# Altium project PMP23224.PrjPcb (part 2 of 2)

## Sheet PMP23224_ACF_secondary.SchDoc
size 431 x 279 mm; Date: Not shown in title block; ApprovedBy: Not shown in title block; CheckedBy: Not shown in title block; Author: Not shown in title block; CompanyName: Not shown in title block; Engineer: Not shown in title block; Organization: Not shown in title block; Address1: Not shown in title block; Address2: Not shown in title block; Address3: Not shown in title block; Address4: Not shown in title block; DocumentNumber: 3; Revision: Use project parameter SCH_Rev; SheetNumber: 3; SheetTotal: 3; PageSetup: Record=PageOptions¦CenterHorizontal=True¦CenterVertical=True¦PrintScale=1.00¦XCorrection=1.00¦YCorrection=1.00¦PrintKind=0¦BorderSize=5000000¦LeftOffset=0¦BottomOffset=0¦Orientation=2¦PaperLength=1000¦PaperWidth=1000¦Scale=100¦PaperSource=15¦PrintQuality=600¦MediaType=1¦DitherType=10¦PaperKind=Letter¦PrintScaleMode=1
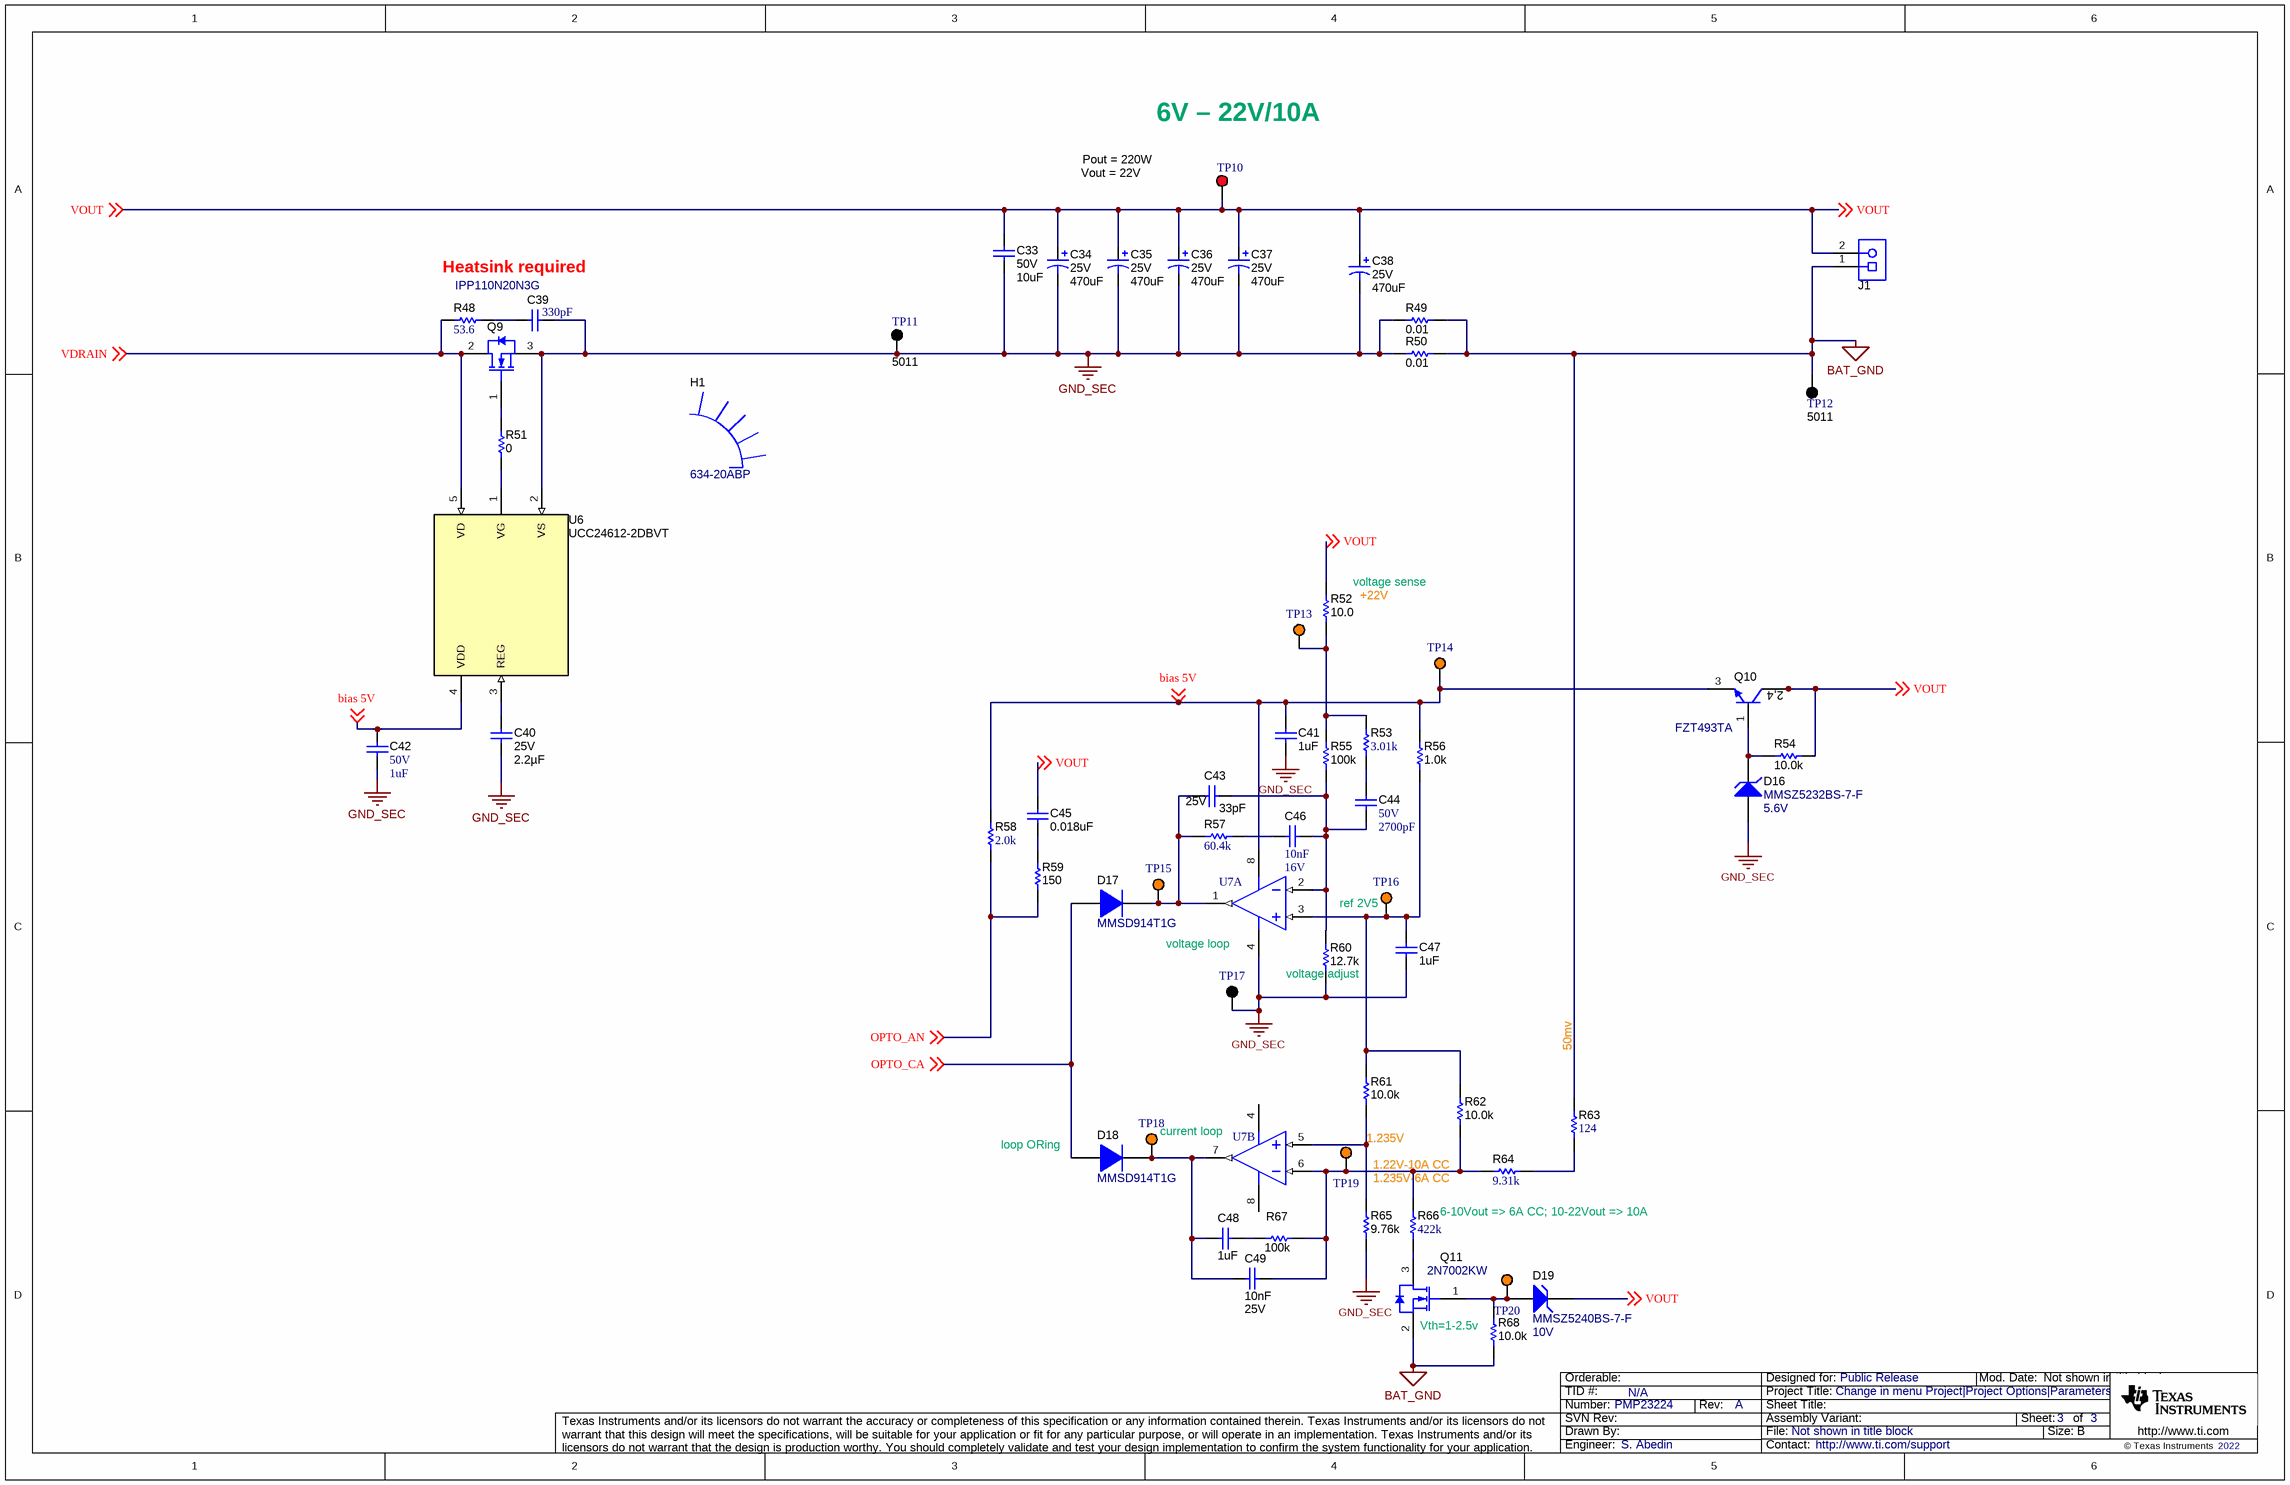
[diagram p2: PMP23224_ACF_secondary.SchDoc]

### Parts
C33  VDC_V: 50V  ValueDisplayed: 10uF  [1210_280]  (hidden comment: C3225X5R1H106K250AB)
C34  VDC_V: 25V  ValueDisplayed: 470uF  [Chemi-Con_1000x1600]  (hidden comment: ELXZ250ELL471MJ16S)
C35  VDC_V: 25V  ValueDisplayed: 470uF  [Chemi-Con_1000x1600]  (hidden comment: ELXZ250ELL471MJ16S)
C36  VDC_V: 25V  ValueDisplayed: 470uF  [Chemi-Con_1000x1600]  (hidden comment: ELXZ250ELL471MJ16S)
C37  VDC_V: 25V  ValueDisplayed: 470uF  [Chemi-Con_1000x1600]  (hidden comment: ELXZ250ELL471MJ16S)
C38  VDC_V: 25V  ValueDisplayed: 470uF  [Chemi-Con_1000x1600]  (hidden comment: ELXZ250ELL471MJ16S)
C39  ValueDisplayed: 330pF  [0805_HV]  (hidden comment: GRM21A5C2E331JW01D)
C40  VDC_V: 25V  ValueDisplayed: 2.2µF  [0603S]  (hidden comment: GRM188C71E225KE11D)
C41  ValueDisplayed: 1uF  [0603S]  (hidden comment: Capacitor)
C42  VDC_V: 50V  ValueDisplayed: 1uF  [0805_HV]  (hidden comment: C2012X5R1H105K125AB)
C43  VDC_V: 25V  ValueDisplayed: 33pF  [0402S]  (hidden comment: GRM1555C1E330JA01D)
C44  VDC_V: 50V  ValueDisplayed: 2700pF  [0402]  (hidden comment: GRM155R71H272KA01D)
C45  ValueDisplayed: 0.018uF  [0402S]  (hidden comment: GRM155R71H183KA12D)
C46  Cap_F: 10nF  VDC_V: 16V  [0603]  (hidden comment: GRM188R71C103KA01D)
C47  ValueDisplayed: 1uF  [0603S]  (hidden comment: Capacitor)
C48  ValueDisplayed: 1uF  [0603S]  (hidden comment: Capacitor)
C49  Cap_F: 10nF  VDC_V: 25V  [0603]  (hidden comment: GRM188R71E103KA01D)
D16  MMSZ5232BS-7-F  value 5.6V  [SOD-323]
D17  MMSD914T1G  [SOD-123]
D18  MMSD914T1G  [SOD-123]
D19  MMSZ5240BS-7-F  value 10V  [SOD-323]
H1  634-20ABP  [HSINK_634-10ABP]
J1  ED120/2DS  [On-Shore_ED120_2DS]  (value not drawn)
Q9  IPP110N20N3G  [TO-220-3]
Q10  FZT493TA  [SOT-223]
Q11  2N7002KW  [SOT-323]
R48  ValueDisplayed: 53.6  [0805_HV]  (hidden comment: RT0805BRD0753R6L)
R49  ValueDisplayed: 0.01  [2010]  (hidden comment: CSRN2010FT10L0)
R50  ValueDisplayed: 0.01  [2010]  (hidden comment: CSRN2010FT10L0)
R51  ValueDisplayed: 0  [0402S]  (hidden comment: CRCW04020000Z0ED)
R52  ValueDisplayed: 10.0  [0402]  (hidden comment: CRCW040210R0FKED)
R53  ValueDisplayed: 3.01k  [0402]  (hidden comment: CRCW04023K01FKED)
R54  ValueDisplayed: 10.0k  [1206]  (hidden comment: CRCW120610K0FKEA)
R55  ValueDisplayed: 100k  [0603S]  (hidden comment: Resistor)
R56  ValueDisplayed: 1.0k  [0603]  (hidden comment: CRCW06031K00JNEA)
R57  ValueDisplayed: 60.4k  [0603]  (hidden comment: CRCW060360K4FKEA)
R58  ValueDisplayed: 2.0k  [0603]  (hidden comment: CRCW06032K00JNEA)
R59  ValueDisplayed: 150  [0402S]  (hidden comment: CRCW0402150RFKED)
R60  ValueDisplayed: 12.7k  [0402S]  (hidden comment: CRCW040212K7FKED)
R61  ValueDisplayed: 10.0k  [TNPW0603]  (hidden comment: TNPW060310K0BEEA)
R62  ValueDisplayed: 10.0k  [TNPW0603]  (hidden comment: TNPW060310K0BEEA)
R63  ValueDisplayed: 124  [0402]  (hidden comment: CRCW0402124RFKED)
R64  ValueDisplayed: 9.31k  [0402]  (hidden comment: CRCW04029K31FKED)
R65  ValueDisplayed: 9.76k  [0603S]  (hidden comment: RG1608P-9761-B-T5)
R66  ValueDisplayed: 422k  [0402]  (hidden comment: CRCW0402422KFKED)
R67  ValueDisplayed: 100k  [0603S]  (hidden comment: Resistor)
R68  ValueDisplayed: 10.0k  [0603S]  (hidden comment: Resistor)
TP10  5010  [Keystone5010]  (value not drawn)
TP11  5011  [Keystone5011]
TP12  5011  [Keystone5011]
TP13  5003  [Keystone5003]  (value not drawn)
TP14  5003  [Keystone5003]  (value not drawn)
TP15  5003  [Keystone5003]  (value not drawn)
TP16  5003  [Keystone5003]  (value not drawn)
TP17  5001  [Keystone5001]  (value not drawn)
TP18  5003  [Keystone5003]  (value not drawn)
TP19  5003  [Keystone5003]  (value not drawn)
TP20  5003  [Keystone5003]  (value not drawn)
U6  UCC24612-2DBVT  [DBV0005A_N]
U7  TI-AMP-D6-2-8_D  [D0008A_N]  (value not drawn)  (parts A,B of 2)

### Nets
BAT_GND: J1.1 Q11.2(S) R49.2 R50.2 R63.2 R68.1 TP12.1
GND_SEC: C33.2 C34.2(-) C35.2(-) C36.2(-) C37.2(-) C38.2(-) C39.1 C40.2 C41.1 C42.2 C47.2 D16.2(A) Q9.3(S) R49.1 R50.1 R60.1 R65.1 TP11.1 TP17.1 U6.2(VS) U7.4(VCC-)
bias 5V: C41.2 C42.1 Q10.3(E) R56.2 R58.2 TP14.1 U6.4(VDD) U7.8(VCC+) ; off-sheet bias 5V
OPTO_AN: R58.1 R59.1 ; off-sheet OPTO_AN
OPTO_CA: D17.2(A) D18.2(A) ; off-sheet OPTO_CA
VDRAIN: Q9.2(D) R48.1 U6.5(VD) ; off-sheet VDRAIN
VOUT: C33.1 C34.1(+) C35.1(+) C36.1(+) C37.1(+) C38.1(+) C45.1 D19.1(K) J1.2 Q10.2(C) Q10.4(C) R52.2 R54.2 TP10.1 ; off-sheet VOUT
NetC39_2: C39.2 R48.2
NetC40_1: C40.1 U6.3(REG)
NetC43_1: C43.1 C44.2 C46.1 R55.1 R60.2 U7.2(IN1-)
NetC43_2: C43.2 D17.1(K) R57.1 TP15.1 U7.1(OUT1)
NetC44_1: C44.1 R53.1
NetC45_2: C45.2 R59.2
NetC46_2: C46.2 R57.2
NetC47_1: C47.1 R56.1 R61.2 R62.2 TP16.1 U7.3(IN1+)
NetC48_1: C48.1 C49.2 D18.1(K) TP18.1 U7.7(OUT2)
NetC48_2: C48.2 R67.2
NetC49_1: C49.1 R62.1 R64.1 R66.2 R67.1 TP19.1 U7.6(IN2-)
NetD16_1: D16.1(K) Q10.1(B) R54.1
NetD19_2: D19.2(A) Q11.1(G) R68.2 TP20.1
NetQ9_1: Q9.1(G) R51.1
NetQ11_3: Q11.3(D) R66.1
NetR51_2: R51.2 U6.1(VG)
NetR52_1: R52.1 R53.2 R55.2 TP13.1
NetR61_1: R61.1 R65.2 U7.5(IN2+)
NetR63_1: R63.1 R64.2

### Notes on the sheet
- Vout = 22V
- Pout = 220W
- 6V – 22V/10A
- Heatsink required
- (near R52) voltage sense
- (near R52) +22V
- (near TP16) ref 2V5
- (near U7) voltage loop
- (near R60) voltage adjust
- 50mv
- (near D18) loop ORing
- current loop
- 1.235V
- 1.22V-10A CC
- 1.235V-6A CC
- 6-10Vout => 6A CC; 10-22Vout => 10A
- Vth=1-2.5v

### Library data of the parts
C33 = CMP-0009103-1: CAP, CERM, 10 uF, 50 V, +/- 10%, X5R, 1210; Manufacturer: TDK; TaMin_C: -55°C; Polarized: N; SizeAreaWB_mm2: 14.7; Value1: Unknown; U/M: EA; Value: 10uF; TaMax_C: 85°C; SizeZ_mm: 2.8; SizeX_mm: 3.2; SizeY_mm: 2.5; Cap_Case: 1210; SizeArea_mm2: 8; Cap_F: 10µF; AEC Category: Q200
C34-C38 = CMP-0010480-1: CAP, AL, 470 uF, 25 V, +/- 20%, AEC-Q200 Grade 2, TH; Manufacturer: Chemi-Con; TaMin_C: -55°C; Polarized: Y; SizeAreaWB_mm2: 144; Value1: Unknown; U/M: EA; Value: 470uF; TaMax_C: 105°C; SizeZ_mm: 17.5; SizeX_mm: 10; Cap_Case: 10x16mm; SizeArea_mm2: 100; CompType: Capacitor; Cap_F: 470µF; IRMS_A: 1.05A; AEC Grade: 2; AEC Category: Q200
C39 = CMP-0081666-1: CAP, CERM, 330 pF, 250 V,+/- 5%, C0G/NP0, 0805; Manufacturer: MuRata; SizeAreaWB_mm2: 6.75; SizeArea_mm2: 2.5; AEC Qualified: N; AEC Category: Q200; Value: 330pF; TaMax_C: 125°C; SizeZ_mm: 1.45; TaMin_C: -55°C; VDC_V: 250V; SizeY_mm: 1.25; U/M: EA; CompType: Capacitor; SizeX_mm: 2; Cap_Case: 0805
C40 = CMP-0075366-1: CAP, CERM, 2.2 µF, 25 V,+/- 10%, X7S, 0603; Manufacturer: MuRata; TaMin_C: -55°C; Polarized: N; SizeAreaWB_mm2: 4.68; U/M: EA; Value: 2.2uF; TaMax_C: 125°C; SizeZ_mm: 1.0; SizeX_mm: 1.6; SizeY_mm: 0.8; Cap_Case: 0603; SizeArea_mm2: 1.28; AEC Category: Q200
C41 C47 C48 = CMP-0007405-4: CAP, CERM, 1 uF, 25 V, +/- 10%, X7R, 0603; PartNumber: GRM188R71E105KA12D; Manufacturer: MuRata; Polarized: N; Value: 1uF; U/M: EA; Cap_F: 1µF; Value1: Unknown; VDC_V: 25V; TaMin_C: -55°C; TaMax_C: 125°C; Cap_Case: 0603; AEC Category: Q200; SizeArea_mm2: 1.28; SizeAreaWB_mm2: 4.68; SizeX_mm: 1.6; SizeY_mm: 0.8; SizeZ_mm: 1
C42 = CMP-0007832-2: CAP, CERM, 1 uF, 50 V, +/- 10%, X5R, 0805; Manufacturer: TDK; TaMin_C: -55°C; ESR_ohm: 8.782m; Polarized: N; SizeAreaWB_mm2: 6.75; Value1: 0.008782 ohm; U/M: EA; Value: 1uF; TaMax_C: 85°C; SizeZ_mm: 1.45; SizeX_mm: 2; SizeY_mm: 1.25; Cap_Case: 0805; SizeArea_mm2: 2.5; Cap_F: 1µF; IRMS_A: 2.20488A; AEC Category: Q200
C43 = CMP-0006377-1: CAP, CERM, 33 pF, 25 V, +/- 5%, C0G/NP0, 0402; Manufacturer: MuRata; TaMin_C: -55°C; Polarized: N; SizeAreaWB_mm2: 3; Value1: Unknown; U/M: EA; Value: 33pF; TaMax_C: 125°C; SizeZ_mm: 0.6; SizeX_mm: 1; SizeY_mm: 0.5; Cap_Case: 0402; AEC Category: Q200
C44 = CMP-0006686-1: CAP, CERM, 2700 pF, 50 V, +/- 10%, X7R, 0402; Manufacturer: MuRata; TaMin_C: -55°C; Polarized: N; SizeAreaWB_mm2: 3; Value1: Unknown; U/M: EA; Value: 2700pF; TaMax_C: 125°C; SizeZ_mm: 0.6; SizeX_mm: 1; SizeY_mm: 0.5; Cap_F: 2.7nF; AEC Category: Q200
C45 = CMP-0006681-2: CAP, CERM, 0.018 uF, 50 V, +/- 10%, X7R, 0402; Manufacturer: MuRata; TaMin_C: -55°C; Polarized: N; SizeAreaWB_mm2: 3; Value1: Unknown; U/M: EA; TaMax_C: 125°C; SizeZ_mm: 0.6; SizeX_mm: 1; SizeY_mm: 0.5; Cap_Case: 0402; Value2: 50V; Cap_F: 18nF; AEC Category: Q200
C46 = CMP-0007377-1: CAP, CERM, 0.01 uF, 16 V, +/- 10%, X7R, 0603; Manufacturer: MuRata; TaMin_C: -55°C; Polarized: N; SizeAreaWB_mm2: 4.68; Value1: Unknown; U/M: EA; Value: 0.01uF; TaMax_C: 125°C; SizeZ_mm: 1; SizeX_mm: 1.6; SizeArea_mm2: 1.28; AEC Category: Q200; SizeY_mm: 0.8
C49 = CMP-0007403-2: CAP, CERM, 0.01 uF, 25 V, +/- 10%, X7R, 0603; Manufacturer: MuRata; TaMin_C: -55°C; Polarized: N; SizeAreaWB_mm2: 4.68; Value1: Unknown; U/M: EA; Value: 0.01uF; TaMax_C: 125°C; SizeZ_mm: 1; SizeX_mm: 1.6; SizeY_mm: 0.8; SizeArea_mm2: 1.28; AEC Category: Q200
D16 = CMP-0005855-3: Diode, Zener, 5.6 V, 200 mW, SOD-323; Manufacturer: Diodes Inc.; SizeZ_mm: 1; SizeX_mm: 2.7; Value1: 0.2W; SizeArea_mm2: 3.645; RJA_CperW: 350; AEC Category: Q101; Power_W: 200mW; SizeAreaWB_mm2: 8.695; SizeY_mm: 1.35
D17 D18 = CMP-0076981-2: Diode, Switching, 100 V, 0.2 A, SOD-123; Manufacturer: ON Semiconductor; Value1: 0.2A; Io_A: 200mA; TJmax_C: 150°C; Green_REACh: Incomplete; SizeY_mm: 1.7; Green_Lifecycle: Not Set; Vr_V: 100V; Value: 100V; SizeZ_mm: 1.35; AEC Category: Q101; SizeAreaWB_mm2: 13.095; SizeX_mm: 3.85; SizeArea_mm2: 6.545
D19 = CMP-0005829-1: Diode, Zener, 10 V, 200 mW, SOD-323; Manufacturer: Diodes Inc.; Power_W: 200mW; SizeAreaWB_mm2: 8.695; Value1: 0.2W; RJA_CperW: 350; U/M: EA; SizeZ_mm: 1; SizeX_mm: 2.7; SizeY_mm: 1.35; SizeArea_mm2: 3.645; AEC Category: Q101
H1 = CMP-0004015-1: Heat Sink, TO-220, TH; Manufacturer: Wakefield Solutions; Key: 634-10ABP
J1 = CMP-0074910-1: Terminal Block, 5.08 mm, 2x1, Brass, TH; Manufacturer: On-Shore Technology; Cert_VDE: Y; CNHeader: False; Current_A: 15A; Green_Lifecycle: Not Set; Shrouded: N; Gender: Female; Green_REACh: Incomplete; Voltage_V: 300V; Row_Count: 1; Pitch_mm: 5.08; CT: True
Q9 = CMP-0860023-1: MOSFET, N-CH, 200 V, 100 A,; Manufacturer: Infineon Technologies; Alternate Manufacturer: None; AEC Category: Q101; Value1: ? ohm; ChType: N; SizeArea_mm2: 86.0552; SizeAreaWB_mm2: 127.3152; ChMode: Enhancement; Value: 200V; QgTyp_nC: 70; IdsMax_A: 100A; SizeX_mm: 8.47; Value2: 70 nC; Vgs_V: 20V; SizeZ_mm: 20.68; SizeY_mm: 10.16
Q10 = CMP-0000473-1: Transistor, NPN, 100 V, 1 A, AEC-Q101, SOT-223; Manufacturer: Diodes Inc.; TaMax_C: 150°C; Value2: 300; Value1: 1 A; Vcesat1_V: 300mV; SizeX_mm: 6.5; SizeY_mm: 7; TaMin_C: -55°C; IcRated_A: 1A; CompType: BJT; SizeZ_mm: 1.6; AEC Qualified: Y; Value: 100 V; SizeArea_mm2: 45.5; NPN: 1; Vceo_V: 100V; PNP: 0; AEC Category: Q101; SizeAreaWB_mm2: 76.5; U/M: EA
Q11 = CMP-0000774-1: MOSFET, N-CH, 60 V, 0.31 A, SOT-323; Alternate Manufacturer: None; Manufacturer: Fairchild Semiconductor; SizeZ_mm: 1.1; ChType: N; Value1: 1; VdsMax_V: 60V; SizeX_mm: 2.2; Vgs_V: 2.1V; Value: 60V; Rdson45_ohm: 1.6; SizeArea_mm2: 4.84; AEC Category: Q101; IdsMax_A: 310mA; SizeAreaWB_mm2: 10.24; U/M: EA
R48 = CMP-0020168-2: RES, 53.6, 0.1%, 0.125 W, 0805; Manufacturer: Yageo America; Power_W: 125mW; TempCo: 25 ppm/C; Value_Code: 53R6; U/M: EA; Value: 53.6; EIA_Code: E192; SizeX_mm: 2; SizeY_mm: 1.25; SizeZ_mm: 1.45; Value2: 0.125W; SizeArea_mm2: 2.5; VDC_V: 150V; AEC Category: Q200
R49 R50 = CMP-0016532-1: RES, 0.01, 1%, 1 W, 2010; Manufacturer: Stackpole Electronics Inc; Power_W: 1W; TempCo: 250 ppm/C; Value_Code: R010; U/M: EA; Value: 0.01; EIA_Code: E96; SizeX_mm: 5; SizeY_mm: 2.5; SizeZ_mm: 1.66; SizeArea_mm2: 12.5; AEC Category: Q200
R51 = CMP-0026822-3: RES, 0, 5%, 0.063 W, AEC-Q200 Grade 0, 0402; Manufacturer: Vishay-Dale; Power_W: 63mW; TempCo: 200 ppm/C; Value_Code: 0000; Value: 0; EIA_Code: E24; SizeX_mm: 1; SizeY_mm: 0.5; SizeZ_mm: 0.6; Value2: 0.063W; CompType: Resistor; AEC Qualified: Y; VDC_V: 50V; AEC Category: Q200
R52 = CMP-0025963-1: RES, 10.0, 1%, 0.063 W, 0402; Manufacturer: Vishay-Dale; Power_W: 63mW; TempCo: 100 ppm/C; Value_Code: 10R0; U/M: EA; Value: 10.0; EIA_Code: E96; Res_ohm: 10; SizeX_mm: 1; SizeY_mm: 0.5; SizeZ_mm: 0.6; Value2: 0.063W; VDC_V: 50V; AEC Category: Q200
R53 = CMP-0026329-1: RES, 3.01 k, 1%, 0.063 W, 0402; Manufacturer: Vishay-Dale; Power_W: 63mW; TempCo: 100 ppm/C; Value_Code: 3k01; U/M: EA; Value: 3.01k; EIA_Code: E96; SizeX_mm: 1; SizeY_mm: 0.5; SizeZ_mm: 0.6; Value2: 0.063W; VDC_V: 50V; AEC Category: Q200
R54 = CMP-0016577-2: RES, 10.0 k, 1%, 0.25 W, 1206; Manufacturer: Vishay-Dale; Power_W: 250mW; TempCo: 100 ppm/C; Value_Code: 10k0; U/M: EA; Value: 10.0k; EIA_Code: E96; Res_ohm: 10k; SizeX_mm: 3.2; SizeY_mm: 1.6; SizeZ_mm: 1.35; Value2: 0.25W; SizeArea_mm2: 5.12; VDC_V: 200V; AEC Category: Q200
R55 R67 = CMP-0021990-4: RES, 100 k, 1%, 0.1 W, AEC-Q200 Grade 0, 0603; PartNumber: CRCW0603100KFKEA; Manufacturer: Vishay-Dale; Value: 100k; Power_W: 100mW; Value2: 0.1W; VDC_V: 75V; TempCo: 100 ppm/C; EIA_Code: E96; AEC Category: Q200; AEC Grade: 0; AEC Qualified: Y; SizeArea_mm2: 1.28; SizeX_mm: 1.6; SizeY_mm: 0.8; SizeZ_mm: 1
R56 = CMP-0025729-1: RES, 1.0 k, 5%, 0.1 W, 0603; Manufacturer: Vishay-Dale; Power_W: 100mW; TempCo: 200 ppm/C; Value_Code: 1k00; U/M: EA; Value: 1.0k; EIA_Code: E24; Res_ohm: 1k; SizeX_mm: 1.6; SizeY_mm: 0.8; SizeZ_mm: 1; Value2: 0.1W; SizeArea_mm2: 1.28; VDC_V: 75V; AEC Category: Q200
R57 = CMP-0022532-2: RES, 60.4 k, 1%, 0.1 W, 0603; Manufacturer: Vishay-Dale; Power_W: 100mW; TempCo: 100 ppm/C; Value_Code: 60k4; U/M: EA; Value: 60.4k; EIA_Code: E96; SizeX_mm: 1.6; SizeY_mm: 0.8; SizeZ_mm: 1; Value2: 0.1W; SizeArea_mm2: 1.28; VDC_V: 75V; AEC Category: Q200
R58 = CMP-0025768-2: RES, 2.0 k, 5%, 0.1 W, 0603; Manufacturer: Vishay-Dale; Power_W: 100mW; TempCo: 200 ppm/C; Value_Code: 2k00; U/M: EA; Value: 2.0k; EIA_Code: E24; Res_ohm: 2k; SizeX_mm: 1.6; SizeY_mm: 0.8; SizeZ_mm: 1; Value2: 0.1W; SizeArea_mm2: 1.28; VDC_V: 75V; AEC Category: Q200
R59 = CMP-0026022-3: RES, 150, 1%, 0.063 W, AEC-Q200 Grade 0, 0402; Manufacturer: Vishay-Dale; Power_W: 63mW; TempCo: 100 ppm/C; Value_Code: 150R; Value: 150; EIA_Code: E96; SizeX_mm: 1; SizeY_mm: 0.5; SizeZ_mm: 0.6; Value2: 0.063W; AEC Qualified: Y; VDC_V: 50V; AEC Category: Q200; AEC Grade: 0
R60 = CMP-0025993-1: RES, 12.7 k, 1%, 0.063 W, 0402; Manufacturer: Vishay-Dale; Power_W: 63mW; TempCo: 100 ppm/C; Value_Code: 12k7; U/M: EA; Value: 12.7k; EIA_Code: E96; SizeX_mm: 1; SizeY_mm: 0.5; SizeZ_mm: 0.6; Value2: 0.063W; VDC_V: 50V; AEC Category: Q200
R61 R62 = CMP-0025686-1: RES, 10.0 k, 0.1%, 0.1 W, AEC-Q200 Grade 1, 0603; Manufacturer: Vishay-Dale; Power_W: 100mW; TempCo: 25 ppm/C; Value_Code: 10k0; U/M: EA; Value: 10.0k; EIA_Code: E192; Res_ohm: 10k; SizeX_mm: 1.6; SizeY_mm: 0.85; SizeZ_mm: 0.55; Value2: 0.1W; SizeArea_mm2: 1.36; AEC Qualified: Y; VDC_V: 75V; AEC Grade: 1; AEC Category: Q200
R63 = CMP-0025987-3: RES, 124, 1%, 0.063 W, AEC-Q200 Grade 0, 0402; Manufacturer: Vishay-Dale; Power_W: 63mW; TempCo: 100 ppm/C; Value_Code: 124R; Value: 124; EIA_Code: E96; SizeX_mm: 1; SizeY_mm: 0.5; SizeZ_mm: 0.6; Value2: 0.063W; AEC Qualified: Y; VDC_V: 50V; AEC Category: Q200; AEC Grade: 0
R64 = CMP-0026620-1: RES, 9.31 k, 1%, 0.063 W, 0402; Manufacturer: Vishay-Dale; Power_W: 63mW; TempCo: 100 ppm/C; Value_Code: 9k31; U/M: EA; Value: 9.31k; EIA_Code: E96; SizeX_mm: 1; SizeY_mm: 0.5; SizeZ_mm: 0.6; Value2: 0.063W; VDC_V: 50V; AEC Category: Q200
R65 = CMP-0023624-3: RES, 9.76 k, 0.1%, 0.1 W, 0603; Manufacturer: Susumu Co Ltd; Power_W: 100mW; TempCo: 25 ppm/C; Value_Code: 9k76; U/M: EA; Value: 9.76k; EIA_Code: E192; SizeX_mm: 1.6; SizeY_mm: 0.8; SizeZ_mm: 1; Value2: 0.1W; SizeArea_mm2: 1.28; VDC_V: 75V; AEC Category: Q200
R66 = CMP-0026373-2: RES, 422 k, 1%, 0.063 W, AEC-Q200 Grade 0, 0402; Manufacturer: Vishay-Dale; Power_W: 63mW; TempCo: 100 ppm/C; Value: 422k; EIA_Code: E96; SizeX_mm: 1; SizeY_mm: 0.5; SizeZ_mm: 0.6; Value2: 0.063W; AEC Qualified: Y; VDC_V: 50V; AEC Category: Q200; AEC Grade: 0
R68 = CMP-0021998-4: RES, 10.0 k, 1%, 0.1 W, AEC-Q200 Grade 0, 0603; PartNumber: CRCW060310K0FKEA; Manufacturer: Vishay-Dale; Value: 10.0k; Res_ohm: 10k; Value_Code: 10k0; Power_W: 100mW; Value2: 0.1W; VDC_V: 75V; TempCo: 100 ppm/C; EIA_Code: E96; AEC Category: Q200; AEC Grade: 0; AEC Qualified: Y; SizeArea_mm2: 1.28; SizeX_mm: 1.6; SizeY_mm: 0.8; SizeZ_mm: 1
TP10 = CMP-0055147-1: Test Point, Multipurpose, Red, TH; Manufacturer: Keystone; ContactFinish: Silver; Green_Lifecycle: Active; Green_REACh: Passed; CNHeader: FALSE; CT: TRUE
TP11 TP12 = CMP-0055148-1: Test Point, Multipurpose, Black, TH; Manufacturer: Keystone; ContactFinish: Silver; Green_Lifecycle: Active; Green_REACh: Passed; CNHeader: FALSE; CT: TRUE
TP13-TP16 TP18-TP20 = CMP-0055140-1: Test Point, Miniature, Orange, TH; Manufacturer: Keystone; CNHeader: FALSE; ContactFinish: Silver; CT: TRUE; Green_Lifecycle: Active; Green_REACh: Passed
TP17 = CMP-0055138-1: Test Point, Miniature, Black, TH; Manufacturer: Keystone; CNHeader: FALSE; ContactFinish: Silver; CT: TRUE; Green_Lifecycle: Active; Green_REACh: Passed
U6 = CMP-0013047-3: High-Frequency Multi-Mode Synchronous Rectifier Controller, DBV0005A (SOT-23-5); Manufacturer: Texas Instruments; Alternate PartNumber: UCC24612-2DBVR; SizeX_mm: 2.8; SizeY_mm: 2.9; CompType: IC; SizeZ_mm: 1.45; SizeArea_mm2: 8.12; SizeAreaWB_mm2: 14.82; AEC Category: Q200; AEC Qualified: N
U7 = CMP-0043686-1: Dual Operational Amplifier with Internal Reference, 3 to 32 V, -40 to 105 degC, 8-pin SOIC (D8), Green (RoHS & no Sb/Br); PartNumber: TL103WAID; Manufacturer: Texas Instruments; CMRR(Min)(dB): 70; GBW(Typ)(MHz): 0.9; IIB(Max)(pA): 150000; Iq per channel(Max)(mA): 0.6; Number of Channels: 2; Offset Drift(Typ)(uV/C): 7; Rating: Catalog; Slew Rate(Typ)(V/us): 0.4; Sub Family: General Purpose Amplifier, High Supply Voltage Amplifier (>=30V); Total Supply Voltage(Max)(+5V is 5, +/-5V is 10): 32; Total Supply Voltage(Min)(+5V is 5, +/-5V is 10): 3; Vn at 1kHz(Typ)(nV/rtHz): 50

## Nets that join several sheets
GND: PMP23224 (19 pins), PMP23224_BlankSheet (13 pins)
GND_SEC: PMP23224_BlankSheet (C21.1), PMP23224_ACF_secondary (21 pins)
HV: PMP23224 (6 pins), PMP23224_BlankSheet (C17.1 C18.1 R24.2 T1.1)
OPTO_AN: PMP23224_BlankSheet (U5.1), PMP23224_ACF_secondary (R58.1 R59.1)
OPTO_CA: PMP23224_BlankSheet (U5.2), PMP23224_ACF_secondary (D17.2 D18.2)
VDD: PMP23224 (D5.2), PMP23224_BlankSheet (D7.1 TP1.1)
VDRAIN: PMP23224_BlankSheet (T1.7 T1.8), PMP23224_ACF_secondary (Q9.2 R48.1 U6.5)
VOUT: PMP23224_BlankSheet (T1.5 T1.6), PMP23224_ACF_secondary (14 pins)

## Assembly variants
001: not fitted C39 C43 C45 C48 D11 Q7 R32 R34 R40 R48 R59 R67 U3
